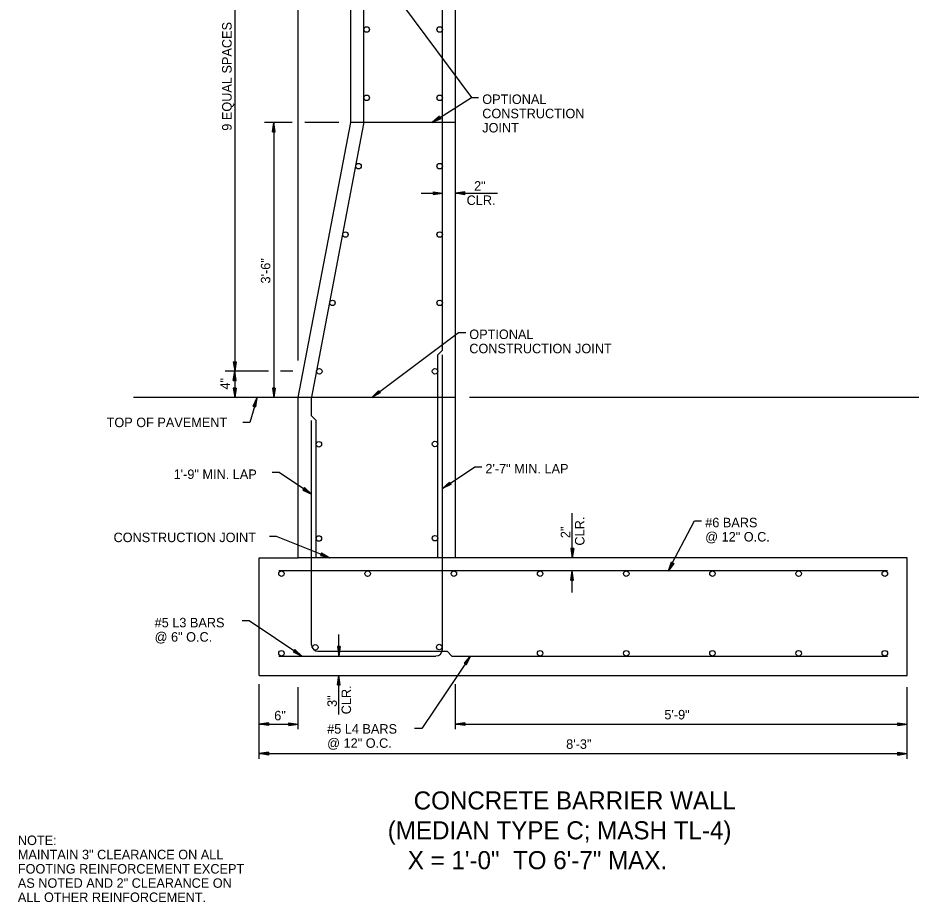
# Model space of a CAD drawing. Extents: x 757924.6 to 757955.2, y 1657125.5 to 1657146.2.
# Drawn here: x 757933.28 to 757944.65, y 1657125.61 to 1657136.87 of the extents above; entities that cross this region are included whole.
import ezdxf

# ---------------------------------------------------------------- set-up
doc = ezdxf.new("R2010")
doc.units = 0
for name, color, linetype in [('1', 7, 'Continuous'), ('10', 7, 'Continuous'), ('2', 7, 'Continuous'), ('7', 7, 'Continuous'), ('9', 7, 'Continuous')]:
    doc.layers.add(name, color=color, linetype=linetype)

msp = doc.modelspace()

# ---------------------------------------------------------------- linework, layer by layer
at = {"layer": '1'}
for p, q in [((757937.517, 1657135.539), (757937.517, 1657140.539)), ((757937.684, 1657135.523), (757937.684, 1657140.289)), ((757938.684, 1657132.641), (757938.684, 1657137.023)), ((757938.85, 1657129.997), (757938.85, 1657137.039)), ((757936.85, 1657132.039), (757937.517, 1657135.539)), ((757937.017, 1657132.023), (757937.684, 1657135.523)), ((757938.85, 1657135.539), (757937.517, 1657135.539)), ((757938.684, 1657132.641), (757938.624, 1657132.581)), ((757938.624, 1657129.997), (757938.624, 1657132.581)), ((757938.684, 1657128.831), (757938.684, 1657132.581)), ((757936.85, 1657132.039), (757934.75, 1657132.039)), ((757936.85, 1657129.997), (757936.85, 1657132.039)), ((757938.85, 1657132.039), (757936.85, 1657132.039)), ((757937.017, 1657131.807), (757937.017, 1657132.023)), ((757937.017, 1657131.807), (757937.077, 1657131.747)), ((757937.017, 1657128.891), (757937.017, 1657131.747)), ((757937.077, 1657129.997), (757937.077, 1657131.747)), ((757936.35, 1657128.497), (757936.35, 1657129.997)), ((757936.35, 1657129.997), (757936.85, 1657129.997)), ((757938.85, 1657129.997), (757936.85, 1657129.997)), ((757944.6, 1657129.997), (757938.85, 1657129.997)), ((757944.6, 1657128.497), (757944.6, 1657129.997)), ((757944.35, 1657129.831), (757936.6, 1657129.831)), ((757937.1, 1657128.807), (757938.744, 1657128.807)), ((757938.744, 1657128.807), (757938.804, 1657128.747)), ((757936.6, 1657128.747), (757938.6, 1657128.747)), ((757938.804, 1657128.747), (757944.35, 1657128.747)), ((757936.35, 1657128.497), (757944.6, 1657128.497))]:
    msp.add_line(p, q, dxfattribs=at)
for centre in [(757937.719, 1657136.724), (757938.649, 1657136.724), (757937.719, 1657135.854), (757938.649, 1657135.854), (757937.616, 1657134.984), (757938.649, 1657134.984), (757937.45, 1657134.113), (757938.649, 1657134.113), (757937.284, 1657133.243), (757938.649, 1657133.243), (757937.118, 1657132.372), (757938.589, 1657132.372), (757937.112, 1657131.443), (757938.589, 1657131.447), (757937.112, 1657130.243), (757938.589, 1657130.247), (757936.635, 1657129.796), (757937.732, 1657129.796), (757938.83, 1657129.796), (757939.927, 1657129.796), (757941.024, 1657129.796), (757942.121, 1657129.796), (757943.218, 1657129.796), (757944.315, 1657129.796), (757936.635, 1657128.782), (757937.066, 1657128.857), (757938.643, 1657128.861), (757939.927, 1657128.782), (757941.024, 1657128.782), (757942.121, 1657128.782), (757943.218, 1657128.782), (757944.315, 1657128.782)]:
    msp.add_circle(centre, 0.0349, dxfattribs=at)
for centre, start, end in [((757937.1, 1657128.891), 180, 270), ((757938.6, 1657128.831), 270, 0)]:
    msp.add_arc(centre, 0.0833, start, end, dxfattribs=at)
at = {"layer": '7'}
for p, q in [((757938.645, 1657135.619), (757938.554, 1657135.539)), ((757938.645, 1657135.619), (757938.664, 1657135.588)), ((757936.521, 1657135.42), (757936.54, 1657135.539)), ((757936.524, 1657135.42), (757936.54, 1657135.52)), ((757936.557, 1657135.42), (757936.54, 1657135.539)), ((757936.554, 1657135.42), (757936.54, 1657135.52)), ((757938.664, 1657135.588), (757938.554, 1657135.539)), ((757938.647, 1657135.616), (757938.571, 1657135.55)), ((757938.662, 1657135.591), (757938.571, 1657135.55)), ((757938.648, 1657135.613), (757938.588, 1657135.561)), ((757938.661, 1657135.594), (757938.588, 1657135.561)), ((757938.65, 1657135.611), (757938.605, 1657135.572)), ((757938.659, 1657135.596), (757938.605, 1657135.572)), ((757938.651, 1657135.608), (757938.621, 1657135.582)), ((757938.657, 1657135.599), (757938.621, 1657135.582)), ((757938.653, 1657135.606), (757938.638, 1657135.593)), ((757938.656, 1657135.601), (757938.638, 1657135.593)), ((757936.521, 1657135.42), (757936.557, 1657135.42)), ((757936.528, 1657135.42), (757936.54, 1657135.499)), ((757936.53, 1657135.42), (757936.54, 1657135.478)), ((757936.534, 1657135.42), (757936.54, 1657135.459)), ((757936.537, 1657135.42), (757936.54, 1657135.439)), ((757936.551, 1657135.42), (757936.54, 1657135.499)), ((757936.548, 1657135.42), (757936.54, 1657135.478)), ((757936.545, 1657135.42), (757936.54, 1657135.459)), ((757936.542, 1657135.42), (757936.54, 1657135.439)), ((757938.565, 1657134.658), (757938.684, 1657134.64)), ((757938.565, 1657134.658), (757938.565, 1657134.622)), ((757938.565, 1657134.655), (757938.664, 1657134.64)), ((757938.565, 1657134.652), (757938.643, 1657134.64)), ((757938.565, 1657134.649), (757938.623, 1657134.64)), ((757938.565, 1657134.646), (757938.603, 1657134.64)), ((757938.565, 1657134.643), (757938.583, 1657134.64)), ((757938.565, 1657134.622), (757938.684, 1657134.64)), ((757938.565, 1657134.635), (757938.603, 1657134.64)), ((757938.565, 1657134.629), (757938.643, 1657134.64)), ((757938.565, 1657134.626), (757938.664, 1657134.64)), ((757938.565, 1657134.632), (757938.623, 1657134.64)), ((757938.565, 1657134.637), (757938.583, 1657134.64)), ((757938.97, 1657134.658), (757938.85, 1657134.64)), ((757938.97, 1657134.621), (757938.85, 1657134.64)), ((757938.97, 1657134.655), (757938.871, 1657134.64)), ((757938.97, 1657134.625), (757938.871, 1657134.64)), ((757938.97, 1657134.651), (757938.891, 1657134.64)), ((757938.97, 1657134.628), (757938.891, 1657134.64)), ((757938.97, 1657134.649), (757938.911, 1657134.64)), ((757938.97, 1657134.631), (757938.911, 1657134.64)), ((757938.97, 1657134.645), (757938.931, 1657134.64)), ((757938.97, 1657134.634), (757938.931, 1657134.64)), ((757938.97, 1657134.642), (757938.951, 1657134.64)), ((757938.97, 1657134.637), (757938.951, 1657134.64)), ((757938.97, 1657134.621), (757938.97, 1657134.658)), ((757936.021, 1657132.492), (757936.04, 1657132.373)), ((757936.021, 1657132.492), (757936.057, 1657132.492)), ((757936.024, 1657132.492), (757936.04, 1657132.392)), ((757936.028, 1657132.492), (757936.04, 1657132.413)), ((757936.03, 1657132.492), (757936.04, 1657132.433)), ((757936.034, 1657132.492), (757936.04, 1657132.453)), ((757936.037, 1657132.492), (757936.04, 1657132.473)), ((757936.057, 1657132.492), (757936.04, 1657132.373)), ((757936.045, 1657132.492), (757936.04, 1657132.453)), ((757936.051, 1657132.492), (757936.04, 1657132.413)), ((757936.054, 1657132.492), (757936.04, 1657132.392)), ((757936.048, 1657132.492), (757936.04, 1657132.433)), ((757936.042, 1657132.492), (757936.04, 1657132.473)), ((757936.021, 1657132.254), (757936.04, 1657132.373)), ((757936.024, 1657132.254), (757936.04, 1657132.353)), ((757936.028, 1657132.254), (757936.04, 1657132.332)), ((757936.057, 1657132.254), (757936.04, 1657132.373)), ((757936.054, 1657132.254), (757936.04, 1657132.353)), ((757936.051, 1657132.254), (757936.04, 1657132.332)), ((757936.021, 1657132.254), (757936.057, 1657132.254)), ((757936.03, 1657132.254), (757936.04, 1657132.312)), ((757936.034, 1657132.254), (757936.04, 1657132.292)), ((757936.037, 1657132.254), (757936.04, 1657132.272)), ((757936.048, 1657132.254), (757936.04, 1657132.312)), ((757936.045, 1657132.254), (757936.04, 1657132.292)), ((757936.042, 1657132.254), (757936.04, 1657132.272)), ((757936.022, 1657132.159), (757936.04, 1657132.039)), ((757936.057, 1657132.159), (757936.022, 1657132.159)), ((757936.025, 1657132.159), (757936.04, 1657132.059)), ((757936.028, 1657132.159), (757936.04, 1657132.08)), ((757936.031, 1657132.159), (757936.04, 1657132.1)), ((757936.034, 1657132.159), (757936.04, 1657132.12)), ((757936.037, 1657132.159), (757936.04, 1657132.14)), ((757936.057, 1657132.159), (757936.04, 1657132.039)), ((757936.046, 1657132.159), (757936.04, 1657132.12)), ((757936.052, 1657132.159), (757936.04, 1657132.08)), ((757936.054, 1657132.159), (757936.04, 1657132.059)), ((757936.049, 1657132.159), (757936.04, 1657132.1)), ((757936.042, 1657132.159), (757936.04, 1657132.14)), ((757936.522, 1657132.159), (757936.54, 1657132.039)), ((757936.557, 1657132.159), (757936.522, 1657132.159)), ((757936.525, 1657132.159), (757936.54, 1657132.059)), ((757936.528, 1657132.159), (757936.54, 1657132.08)), ((757936.531, 1657132.159), (757936.54, 1657132.1)), ((757936.534, 1657132.159), (757936.54, 1657132.12)), ((757936.537, 1657132.159), (757936.54, 1657132.14)), ((757936.557, 1657132.159), (757936.54, 1657132.039)), ((757936.546, 1657132.159), (757936.54, 1657132.12)), ((757936.552, 1657132.159), (757936.54, 1657132.08)), ((757936.554, 1657132.159), (757936.54, 1657132.059)), ((757936.549, 1657132.159), (757936.54, 1657132.1)), ((757936.542, 1657132.159), (757936.54, 1657132.14)), ((757937.871, 1657132.125), (757937.786, 1657132.039)), ((757937.892, 1657132.096), (757937.786, 1657132.039)), ((757937.873, 1657132.123), (757937.802, 1657132.051)), ((757937.891, 1657132.099), (757937.802, 1657132.051)), ((757937.875, 1657132.12), (757937.818, 1657132.063)), ((757937.889, 1657132.102), (757937.818, 1657132.063)), ((757937.876, 1657132.118), (757937.835, 1657132.075)), ((757937.887, 1657132.103), (757937.835, 1657132.075)), ((757937.878, 1657132.115), (757937.85, 1657132.087)), ((757937.885, 1657132.106), (757937.85, 1657132.087)), ((757937.88, 1657132.113), (757937.867, 1657132.099)), ((757937.883, 1657132.109), (757937.867, 1657132.099)), ((757937.871, 1657132.125), (757937.892, 1657132.096)), ((757936.276, 1657131.93), (757936.327, 1657132.039)), ((757936.279, 1657131.929), (757936.322, 1657132.02)), ((757936.282, 1657131.928), (757936.316, 1657132)), ((757936.285, 1657131.927), (757936.31, 1657131.981)), ((757936.302, 1657131.922), (757936.31, 1657131.981)), ((757936.304, 1657131.921), (757936.316, 1657132)), ((757936.308, 1657131.92), (757936.322, 1657132.02)), ((757936.311, 1657131.92), (757936.327, 1657132.039)), ((757936.276, 1657131.93), (757936.311, 1657131.92)), ((757936.288, 1657131.926), (757936.305, 1657131.962)), ((757936.291, 1657131.925), (757936.299, 1657131.943)), ((757936.296, 1657131.924), (757936.299, 1657131.943)), ((757936.299, 1657131.923), (757936.305, 1657131.962)), ((757938.773, 1657130.962), (757938.684, 1657130.88)), ((757938.775, 1657130.959), (757938.7, 1657130.891)), ((757938.776, 1657130.956), (757938.717, 1657130.903)), ((757938.773, 1657130.962), (757938.793, 1657130.932)), ((757936.928, 1657130.891), (757936.908, 1657130.86)), ((757936.908, 1657130.86), (757937.017, 1657130.809)), ((757936.909, 1657130.863), (757937, 1657130.82)), ((757936.911, 1657130.866), (757936.983, 1657130.831)), ((757936.913, 1657130.868), (757936.967, 1657130.843)), ((757936.915, 1657130.871), (757936.95, 1657130.853)), ((757936.916, 1657130.873), (757936.934, 1657130.865)), ((757936.919, 1657130.878), (757936.934, 1657130.865)), ((757936.921, 1657130.88), (757936.95, 1657130.853)), ((757936.923, 1657130.883), (757936.967, 1657130.843)), ((757936.924, 1657130.885), (757936.983, 1657130.831)), ((757936.926, 1657130.888), (757937, 1657130.82)), ((757936.928, 1657130.891), (757937.017, 1657130.809)), ((757938.793, 1657130.932), (757938.684, 1657130.88)), ((757938.791, 1657130.934), (757938.7, 1657130.891)), ((757938.789, 1657130.937), (757938.717, 1657130.903)), ((757938.778, 1657130.954), (757938.734, 1657130.914)), ((757938.788, 1657130.939), (757938.734, 1657130.914)), ((757938.78, 1657130.952), (757938.75, 1657130.925)), ((757938.786, 1657130.942), (757938.75, 1657130.925)), ((757938.781, 1657130.949), (757938.767, 1657130.936)), ((757938.784, 1657130.945), (757938.767, 1657130.936)), ((757937.147, 1657130.059), (757937.134, 1657130.025)), ((757937.143, 1657130.047), (757937.177, 1657130.027)), ((757937.144, 1657130.05), (757937.195, 1657130.02)), ((757937.145, 1657130.053), (757937.214, 1657130.012)), ((757937.146, 1657130.055), (757937.233, 1657130.005)), ((757937.147, 1657130.059), (757937.252, 1657129.997)), ((757940.319, 1657130.117), (757940.337, 1657129.997)), ((757940.355, 1657130.117), (757940.319, 1657130.117)), ((757940.322, 1657130.117), (757940.337, 1657130.018)), ((757940.325, 1657130.117), (757940.337, 1657130.039)), ((757940.328, 1657130.117), (757940.337, 1657130.058)), ((757940.331, 1657130.117), (757940.337, 1657130.078)), ((757940.334, 1657130.117), (757940.337, 1657130.098)), ((757940.355, 1657130.117), (757940.337, 1657129.997)), ((757940.343, 1657130.117), (757940.337, 1657130.078)), ((757940.349, 1657130.117), (757940.337, 1657130.039)), ((757940.352, 1657130.117), (757940.337, 1657130.018)), ((757940.346, 1657130.117), (757940.337, 1657130.058)), ((757940.34, 1657130.117), (757940.337, 1657130.098)), ((757937.134, 1657130.025), (757937.252, 1657129.997)), ((757937.135, 1657130.028), (757937.233, 1657130.005)), ((757937.136, 1657130.031), (757937.214, 1657130.012)), ((757937.137, 1657130.033), (757937.195, 1657130.02)), ((757937.138, 1657130.037), (757937.177, 1657130.027)), ((757937.14, 1657130.039), (757937.158, 1657130.035)), ((757937.142, 1657130.044), (757937.158, 1657130.035)), ((757941.596, 1657129.943), (757941.557, 1657129.829)), ((757941.599, 1657129.942), (757941.566, 1657129.847)), ((757941.602, 1657129.94), (757941.576, 1657129.865)), ((757941.604, 1657129.939), (757941.585, 1657129.882)), ((757941.607, 1657129.937), (757941.594, 1657129.9)), ((757941.596, 1657129.943), (757941.628, 1657129.927)), ((757941.609, 1657129.936), (757941.603, 1657129.918)), ((757941.614, 1657129.934), (757941.603, 1657129.918)), ((757940.318, 1657129.712), (757940.337, 1657129.831)), ((757940.354, 1657129.712), (757940.337, 1657129.831)), ((757941.628, 1657129.927), (757941.557, 1657129.829)), ((757941.625, 1657129.928), (757941.566, 1657129.847)), ((757941.622, 1657129.93), (757941.576, 1657129.865)), ((757941.62, 1657129.931), (757941.585, 1657129.882)), ((757941.617, 1657129.932), (757941.594, 1657129.9)), ((757940.318, 1657129.712), (757940.354, 1657129.712)), ((757940.321, 1657129.712), (757940.337, 1657129.811)), ((757940.325, 1657129.712), (757940.337, 1657129.79)), ((757940.327, 1657129.712), (757940.337, 1657129.77)), ((757940.331, 1657129.712), (757940.337, 1657129.75)), ((757940.334, 1657129.712), (757940.337, 1657129.73)), ((757940.351, 1657129.712), (757940.337, 1657129.811)), ((757940.348, 1657129.712), (757940.337, 1657129.79)), ((757940.345, 1657129.712), (757940.337, 1657129.77)), ((757940.342, 1657129.712), (757940.337, 1657129.75)), ((757940.339, 1657129.712), (757940.337, 1657129.73)), ((757936.804, 1657128.829), (757936.784, 1657128.799)), ((757936.784, 1657128.799), (757936.893, 1657128.747)), ((757936.785, 1657128.802), (757936.876, 1657128.759)), ((757936.787, 1657128.804), (757936.859, 1657128.77)), ((757936.789, 1657128.806), (757936.843, 1657128.781)), ((757936.791, 1657128.809), (757936.826, 1657128.792)), ((757936.792, 1657128.812), (757936.809, 1657128.803)), ((757936.795, 1657128.816), (757936.809, 1657128.803)), ((757936.797, 1657128.819), (757936.826, 1657128.792)), ((757936.799, 1657128.821), (757936.843, 1657128.781)), ((757936.8, 1657128.824), (757936.859, 1657128.77)), ((757936.802, 1657128.826), (757936.876, 1657128.759)), ((757936.804, 1657128.829), (757936.893, 1657128.747)), ((757937.348, 1657128.867), (757937.366, 1657128.747)), ((757937.384, 1657128.867), (757937.348, 1657128.867)), ((757937.351, 1657128.867), (757937.366, 1657128.768)), ((757937.355, 1657128.867), (757937.366, 1657128.789)), ((757937.357, 1657128.867), (757937.366, 1657128.808)), ((757937.361, 1657128.867), (757937.366, 1657128.828)), ((757937.364, 1657128.867), (757937.366, 1657128.848)), ((757937.384, 1657128.867), (757937.366, 1657128.747)), ((757937.372, 1657128.867), (757937.366, 1657128.828)), ((757937.378, 1657128.867), (757937.366, 1657128.789)), ((757937.381, 1657128.867), (757937.366, 1657128.768)), ((757937.375, 1657128.867), (757937.366, 1657128.808)), ((757937.369, 1657128.867), (757937.366, 1657128.848)), ((757938.96, 1657128.658), (757939.042, 1657128.747)), ((757938.963, 1657128.656), (757939.03, 1657128.731)), ((757938.965, 1657128.655), (757939.019, 1657128.714)), ((757938.968, 1657128.653), (757939.008, 1657128.697)), ((757938.983, 1657128.643), (757939.008, 1657128.697)), ((757938.985, 1657128.642), (757939.019, 1657128.714)), ((757938.988, 1657128.64), (757939.03, 1657128.731)), ((757938.99, 1657128.638), (757939.042, 1657128.747)), ((757938.96, 1657128.658), (757938.99, 1657128.638)), ((757938.97, 1657128.651), (757938.997, 1657128.681)), ((757938.973, 1657128.65), (757938.986, 1657128.664)), ((757938.977, 1657128.647), (757938.986, 1657128.664)), ((757938.98, 1657128.645), (757938.997, 1657128.681)), ((757937.347, 1657128.378), (757937.366, 1657128.497)), ((757937.35, 1657128.378), (757937.366, 1657128.478)), ((757937.354, 1657128.378), (757937.366, 1657128.457)), ((757937.384, 1657128.378), (757937.366, 1657128.497)), ((757937.38, 1657128.378), (757937.366, 1657128.478)), ((757937.377, 1657128.378), (757937.366, 1657128.457)), ((757937.347, 1657128.378), (757937.384, 1657128.378)), ((757937.356, 1657128.378), (757937.366, 1657128.437)), ((757937.36, 1657128.378), (757937.366, 1657128.417)), ((757937.363, 1657128.378), (757937.366, 1657128.397)), ((757937.374, 1657128.378), (757937.366, 1657128.437)), ((757937.371, 1657128.378), (757937.366, 1657128.417)), ((757937.368, 1657128.378), (757937.366, 1657128.397)), ((757936.469, 1657127.897), (757936.35, 1657127.879)), ((757936.469, 1657127.895), (757936.37, 1657127.879)), ((757936.469, 1657127.891), (757936.391, 1657127.879)), ((757936.469, 1657127.889), (757936.411, 1657127.879)), ((757936.469, 1657127.897), (757936.469, 1657127.861)), ((757936.731, 1657127.897), (757936.85, 1657127.879)), ((757936.731, 1657127.861), (757936.731, 1657127.897)), ((757936.731, 1657127.894), (757936.83, 1657127.879)), ((757936.731, 1657127.891), (757936.81, 1657127.879)), ((757936.731, 1657127.888), (757936.79, 1657127.879)), ((757938.969, 1657127.897), (757938.85, 1657127.879)), ((757938.969, 1657127.895), (757938.87, 1657127.879)), ((757938.969, 1657127.891), (757938.891, 1657127.879)), ((757938.969, 1657127.889), (757938.911, 1657127.879)), ((757938.969, 1657127.897), (757938.969, 1657127.861)), ((757944.481, 1657127.897), (757944.6, 1657127.879)), ((757944.481, 1657127.861), (757944.481, 1657127.897)), ((757944.481, 1657127.894), (757944.58, 1657127.879)), ((757944.481, 1657127.891), (757944.56, 1657127.879)), ((757944.481, 1657127.888), (757944.54, 1657127.879)), ((757936.469, 1657127.861), (757936.35, 1657127.879)), ((757936.469, 1657127.865), (757936.37, 1657127.879)), ((757936.469, 1657127.868), (757936.391, 1657127.879)), ((757936.469, 1657127.871), (757936.411, 1657127.879)), ((757936.469, 1657127.885), (757936.431, 1657127.879)), ((757936.469, 1657127.874), (757936.431, 1657127.879)), ((757936.469, 1657127.882), (757936.451, 1657127.879)), ((757936.469, 1657127.877), (757936.451, 1657127.879)), ((757936.731, 1657127.885), (757936.769, 1657127.879)), ((757936.731, 1657127.882), (757936.75, 1657127.879)), ((757936.731, 1657127.861), (757936.85, 1657127.879)), ((757936.731, 1657127.873), (757936.769, 1657127.879)), ((757936.731, 1657127.867), (757936.81, 1657127.879)), ((757936.731, 1657127.864), (757936.83, 1657127.879)), ((757936.731, 1657127.87), (757936.79, 1657127.879)), ((757936.731, 1657127.877), (757936.75, 1657127.879)), ((757938.969, 1657127.861), (757938.85, 1657127.879)), ((757938.969, 1657127.865), (757938.87, 1657127.879)), ((757938.969, 1657127.868), (757938.891, 1657127.879)), ((757938.969, 1657127.871), (757938.911, 1657127.879)), ((757938.969, 1657127.885), (757938.931, 1657127.879)), ((757938.969, 1657127.874), (757938.931, 1657127.879)), ((757938.969, 1657127.882), (757938.951, 1657127.879)), ((757938.969, 1657127.877), (757938.951, 1657127.879)), ((757944.481, 1657127.885), (757944.519, 1657127.879)), ((757944.481, 1657127.882), (757944.5, 1657127.879)), ((757944.481, 1657127.861), (757944.6, 1657127.879)), ((757944.481, 1657127.873), (757944.519, 1657127.879)), ((757944.481, 1657127.867), (757944.56, 1657127.879)), ((757944.481, 1657127.864), (757944.58, 1657127.879)), ((757944.481, 1657127.87), (757944.54, 1657127.879)), ((757944.481, 1657127.877), (757944.5, 1657127.879)), ((757936.469, 1657127.522), (757936.35, 1657127.504)), ((757936.469, 1657127.486), (757936.35, 1657127.504)), ((757936.469, 1657127.52), (757936.37, 1657127.504)), ((757936.469, 1657127.49), (757936.37, 1657127.504)), ((757936.469, 1657127.516), (757936.391, 1657127.504)), ((757936.469, 1657127.493), (757936.391, 1657127.504)), ((757936.469, 1657127.514), (757936.411, 1657127.504)), ((757936.469, 1657127.496), (757936.411, 1657127.504)), ((757936.469, 1657127.51), (757936.431, 1657127.504)), ((757936.469, 1657127.499), (757936.431, 1657127.504)), ((757936.469, 1657127.507), (757936.451, 1657127.504)), ((757936.469, 1657127.502), (757936.451, 1657127.504)), ((757936.469, 1657127.522), (757936.469, 1657127.486)), ((757944.481, 1657127.522), (757944.6, 1657127.504)), ((757944.481, 1657127.486), (757944.481, 1657127.522)), ((757944.481, 1657127.519), (757944.58, 1657127.504)), ((757944.481, 1657127.516), (757944.56, 1657127.504)), ((757944.481, 1657127.513), (757944.54, 1657127.504)), ((757944.481, 1657127.51), (757944.519, 1657127.504)), ((757944.481, 1657127.507), (757944.5, 1657127.504)), ((757944.481, 1657127.486), (757944.6, 1657127.504)), ((757944.481, 1657127.498), (757944.519, 1657127.504)), ((757944.481, 1657127.492), (757944.56, 1657127.504)), ((757944.481, 1657127.489), (757944.58, 1657127.504)), ((757944.481, 1657127.495), (757944.54, 1657127.504)), ((757944.481, 1657127.502), (757944.5, 1657127.504))]:
    msp.add_line(p, q, dxfattribs=at)
at = {"layer": '9'}
for p, q in [((757936.04, 1657138.897), (757936.04, 1657132.373)), ((757936.85, 1657132.51), (757936.85, 1657137.787)), ((757938.178, 1657137.039), (757939.055, 1657135.86)), ((757938.554, 1657135.539), (757939.055, 1657135.86)), ((757939.055, 1657135.86), (757939.145, 1657135.86)), ((757936.772, 1657135.539), (757936.42, 1657135.539)), ((757936.54, 1657135.539), (757936.54, 1657132.039)), ((757937.364, 1657135.539), (757936.931, 1657135.539)), ((757938.415, 1657134.64), (757938.684, 1657134.64)), ((757938.85, 1657134.64), (757939.387, 1657134.64)), ((757937.786, 1657132.039), (757938.89, 1657132.867)), ((757938.89, 1657132.867), (757938.98, 1657132.867)), ((757936.471, 1657132.372), (757935.92, 1657132.372)), ((757936.04, 1657132.372), (757936.04, 1657132.039)), ((757936.781, 1657132.372), (757936.622, 1657132.372)), ((757936.327, 1657132.039), (757936.233, 1657131.722)), ((757945.177, 1657132.039), (757939.028, 1657132.039)), ((757936.233, 1657131.722), (757936.143, 1657131.722)), ((757936.606, 1657131.085), (757936.516, 1657131.085)), ((757937.017, 1657130.809), (757936.606, 1657131.085)), ((757938.684, 1657130.88), (757939.095, 1657131.156)), ((757939.095, 1657131.156), (757939.184, 1657131.156)), ((757940.337, 1657129.997), (757940.337, 1657130.564)), ((757941.557, 1657129.831), (757941.893, 1657130.47)), ((757941.893, 1657130.47), (757941.983, 1657130.47)), ((757936.574, 1657130.268), (757936.484, 1657130.268)), ((757937.252, 1657129.997), (757936.574, 1657130.268)), ((757940.337, 1657129.555), (757940.337, 1657129.831)), ((757936.226, 1657129.196), (757936.136, 1657129.196)), ((757936.893, 1657128.747), (757936.226, 1657129.196)), ((757937.366, 1657128.747), (757937.366, 1657129.019)), ((757939.042, 1657128.747), (757938.42, 1657127.822)), ((757937.366, 1657128.003), (757937.366, 1657128.497)), ((757936.35, 1657127.439), (757936.35, 1657128.387)), ((757936.85, 1657127.816), (757936.85, 1657128.352)), ((757938.85, 1657127.816), (757938.85, 1657128.387)), ((757944.6, 1657127.439), (757944.6, 1657128.352)), ((757936.35, 1657127.879), (757936.85, 1657127.879)), ((757938.42, 1657127.822), (757938.33, 1657127.822)), ((757938.85, 1657127.879), (757944.6, 1657127.879)), ((757936.35, 1657127.504), (757944.6, 1657127.504))]:
    msp.add_line(p, q, dxfattribs=at)

# ---------------------------------------------------------------- texts
at = {"layer": '10'}
for s, p in [('CONCRETE BARRIER WALL', (757938.318, 1657126.793)), ('(MEDIAN TYPE C; MASH TL-4)', (757937.988, 1657126.413)), ('X = 1\'-0"  TO 6\'-7" MAX.', (757938.243, 1657126.033))]:
    msp.add_text(s, height=0.23, dxfattribs=at).set_placement(p)
at = {"layer": '2'}
for s, height, p in [('9 EQUAL SPACES', 0.12095, (757936.001, 1657135.435)), ('3\'-6"', 0.1209, (757936.494, 1657133.49)), ('4"', 0.1209, (757935.979, 1657132.14)), ('CLR.', 0.1209, (757940.492, 1657130.153)), ('2"', 0.1209, (757940.311, 1657130.248)), ('CLR.', 0.1209, (757937.521, 1657128.005)), ('3"', 0.1209, (757937.34, 1657128.099))]:
    msp.add_text(s, height=height, rotation=90, dxfattribs=at).set_placement(p)
for s, height, p in [('OPTIONAL', 0.1208, (757939.191, 1657135.776)), ('CONSTRUCTION', 0.12081, (757939.191, 1657135.594)), ('JOINT', 0.1208, (757939.191, 1657135.413)), ('2"', 0.1209, (757939.087, 1657134.672)), ('CLR.', 0.1209, (757938.992, 1657134.49)), ('OPTIONAL', 0.1208, (757939.026, 1657132.783)), ('CONSTRUCTION JOINT', 0.12081, (757939.026, 1657132.602)), ('TOP OF PAVEMENT', 0.12081, (757934.41, 1657131.661)), ('2\'-7" MIN. LAP', 0.12081, (757939.231, 1657131.072)), ('1\'-9" MIN. LAP', 0.12081, (757935.263, 1657131.001)), ('#6 BARS', 0.1208, (757942.029, 1657130.386)), ('CONSTRUCTION JOINT', 0.12081, (757934.498, 1657130.197)), ('@ 12" O.C.', 0.1208, (757942.029, 1657130.205)), ('#5 L3 BARS', 0.1208, (757935.021, 1657129.112)), ('@ 6" O.C.', 0.1208, (757935.021, 1657128.93)), ('6"', 0.1209, (757936.543, 1657127.928)), ('5\'-9"', 0.1209, (757941.509, 1657127.94)), ('#5 L4 BARS', 0.1208, (757937.217, 1657127.759)), ('@ 12" O.C.', 0.1208, (757937.217, 1657127.578)), ('8\'-3"', 0.1209, (757940.259, 1657127.565)), ('NOTE:', 0.1208, (757933.28, 1657126.34)), ('MAINTAIN 3" CLEARANCE ON ALL', 0.12081, (757933.28, 1657126.159)), ('FOOTING REINFORCEMENT EXCEPT', 0.12081, (757933.28, 1657125.977)), ('AS NOTED AND 2" CLEARANCE ON', 0.12081, (757933.28, 1657125.796)), ('ALL OTHER REINFORCEMENT.', 0.12081, (757933.28, 1657125.615))]:
    msp.add_text(s, height=height, dxfattribs=at).set_placement(p)

doc.saveas('drawing.dxf')
